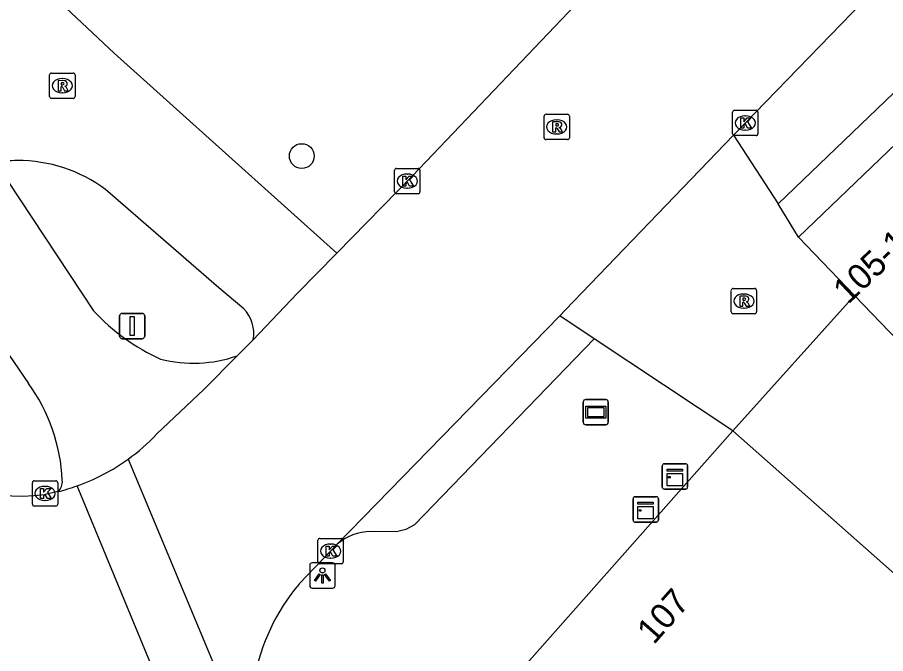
# Model space of a CAD drawing. Extents: x 162812 to 163818, y 381639 to 382470.
# Drawn here: x 162829.9 to 162864.17, y 382025.07 to 382050.18 of the extents above; entities that cross this region are included whole.
import ezdxf

# ---------------------------------------------------------------- set-up
doc = ezdxf.new("R2010")
doc.units = 0
for name, color, linetype in [('IMGEO_Boom', 7, 'Continuous'), ('IMGEO_Fietspad_open', 7, 'Continuous'), ('IMGEO_Kast', 7, 'Continuous'), ('IMGEO_Kolk', 7, 'Continuous'), ('IMGEO_Lichtpunt', 7, 'Continuous'), ('IMGEO_Pand', 7, 'Continuous'), ('IMGEO_Pand_nummerreeks', 7, 'Continuous'), ('IMGEO_Reclamebord', 7, 'Continuous'), ('IMGEO_Rijbaan_lokaal_gesloten', 7, 'Continuous'), ('IMGEO_Rijbaan_lokaal_open', 7, 'Continuous'), ('IMGEO_Rioolput', 7, 'Continuous'), ('IMGEO_Verkeersbordpaal', 7, 'Continuous'), ('IMGEO_Voetpad_open', 7, 'Continuous')]:
    doc.layers.add(name, color=color, linetype=linetype)

msp = doc.modelspace()

# ---------------------------------------------------------------- linework, layer by layer
at = {"layer": 'IMGEO_Boom'}
msp.add_circle((162841.123, 382044.707), 0.489, dxfattribs=at)
at = {"layer": 'IMGEO_Fietspad_open'}
for points in [[(162829.017, 382044.46), (162832.907, 382038.597)], [(162826.137, 382041.866), (162830.332, 382035.729)]]:
    msp.add_lwpolyline(points, dxfattribs=at)
for centre, radius, start, end in [((162838.94, 382044.182), 8.221, 222.7929, 245.6032), ((162836.846, 382041.784), 5.253, 255.653, 289.2539), ((162824.671, 382031.6), 7.007, 2.5444, 36.1079), ((162831.148, 382031.855), 0.526, 311.7184, 6.1382)]:
    msp.add_arc(centre, radius, start, end, dxfattribs=at)
at = {"layer": 'IMGEO_Kast'}
for p, q in [((162855.349, 382031.639), (162855.349, 382032.48)), ((162855.349, 382032.48), (162855.349, 382031.639)), ((162855.424, 382032.564), (162856.265, 382032.564)), ((162856.265, 382032.564), (162855.424, 382032.564)), ((162856.349, 382032.489), (162856.349, 382031.648)), ((162856.349, 382031.648), (162856.349, 382032.489)), ((162854.27, 382031.259), (162855.111, 382031.259)), ((162855.111, 382031.259), (162854.27, 382031.259)), ((162856.274, 382031.564), (162855.433, 382031.564)), ((162855.433, 382031.564), (162856.274, 382031.564)), ((162854.195, 382030.334), (162854.195, 382031.175)), ((162854.195, 382031.175), (162854.195, 382030.334)), ((162855.195, 382031.184), (162855.195, 382030.343)), ((162855.195, 382030.343), (162855.195, 382031.184)), ((162855.12, 382030.259), (162854.279, 382030.259)), ((162854.279, 382030.259), (162855.12, 382030.259))]:
    msp.add_line(p, q, dxfattribs=at)
for points in [[(162855.544, 382032.354), (162856.144, 382032.354), (162856.144, 382032.269), (162855.544, 382032.269), (162855.544, 382032.354)], [(162855.544, 382032.179), (162856.144, 382032.179), (162856.144, 382031.69), (162855.544, 382031.69), (162855.544, 382032.179)], [(162854.39, 382031.049), (162854.99, 382031.049), (162854.99, 382030.964), (162854.39, 382030.964), (162854.39, 382031.049)], [(162854.39, 382030.874), (162854.99, 382030.874), (162854.99, 382030.385), (162854.39, 382030.385), (162854.39, 382030.874)]]:
    msp.add_lwpolyline(points, dxfattribs=at)
for centre in [(162855.628, 382032.028), (162854.474, 382030.723)]:
    msp.add_circle(centre, 0.0377, dxfattribs=at)
for centre, start, end in [((162855.427, 382032.486), 92.4484, 184.2845), ((162855.427, 382032.486), 92.4484, 184.2845), ((162856.271, 382032.486), 2.4484, 94.2845), ((162856.271, 382032.486), 2.4484, 94.2845), ((162855.427, 382031.642), 182.4484, 274.2845), ((162855.427, 382031.642), 182.4484, 274.2845), ((162856.271, 382031.642), 272.4484, 4.2845), ((162856.271, 382031.642), 272.4484, 4.2845), ((162854.273, 382031.181), 92.4484, 184.2845), ((162854.273, 382031.181), 92.4484, 184.2845), ((162855.117, 382031.181), 2.4484, 94.2845), ((162855.117, 382031.181), 2.4484, 94.2845), ((162854.273, 382030.337), 182.4484, 274.2845), ((162854.273, 382030.337), 182.4484, 274.2845), ((162855.117, 382030.337), 272.4484, 4.2845), ((162855.117, 382030.337), 272.4484, 4.2845)]:
    msp.add_arc(centre, 0.0779, start, end, dxfattribs=at)
at = {"layer": 'IMGEO_Kolk'}
for p, q in [((162858.123, 382045.589), (162858.123, 382046.441)), ((162858.198, 382046.515), (162859.05, 382046.515)), ((162859.124, 382046.441), (162859.124, 382045.589)), ((162858.611, 382046.295), (162858.636, 382046.295)), ((162858.634, 382045.735), (162858.609, 382045.735)), ((162859.05, 382045.515), (162858.198, 382045.515)), ((162844.784, 382043.293), (162844.784, 382044.145)), ((162844.859, 382044.219), (162845.711, 382044.219)), ((162845.272, 382043.999), (162845.297, 382043.999)), ((162845.785, 382044.145), (162845.785, 382043.293)), ((162845.295, 382043.439), (162845.27, 382043.439)), ((162845.711, 382043.219), (162844.859, 382043.219)), ((162830.49, 382030.964), (162830.49, 382031.816)), ((162830.565, 382031.89), (162831.417, 382031.89)), ((162830.978, 382031.67), (162831.003, 382031.67)), ((162831.491, 382031.816), (162831.491, 382030.964)), ((162831.417, 382030.89), (162830.565, 382030.89)), ((162831.001, 382031.11), (162830.976, 382031.11)), ((162841.758, 382028.689), (162841.758, 382029.541)), ((162841.833, 382029.615), (162842.685, 382029.615)), ((162842.759, 382029.541), (162842.759, 382028.689)), ((162842.246, 382029.395), (162842.271, 382029.395)), ((162842.269, 382028.835), (162842.244, 382028.835)), ((162842.685, 382028.615), (162841.833, 382028.615))]:
    msp.add_line(p, q, dxfattribs=at)
for points in [[(162858.123, 382045.589), (162858.123, 382046.441)], [(162858.198, 382046.515), (162859.05, 382046.515)], [(162859.124, 382046.441), (162859.124, 382045.589)], [(162858.444, 382046.215), (162858.567, 382046.215), (162858.567, 382046.064), (162858.697, 382046.215), (162858.861, 382046.215), (162858.715, 382046.064), (162858.868, 382045.815), (162858.716, 382045.815), (162858.631, 382045.979), (162858.567, 382045.912), (162858.567, 382045.815), (162858.444, 382045.815), (162858.444, 382046.215)], [(162859.05, 382045.515), (162858.198, 382045.515)], [(162844.784, 382043.293), (162844.784, 382044.145)], [(162844.859, 382044.219), (162845.711, 382044.219)], [(162845.105, 382043.919), (162845.228, 382043.919), (162845.228, 382043.768), (162845.358, 382043.919), (162845.522, 382043.919), (162845.376, 382043.768), (162845.529, 382043.519), (162845.377, 382043.519), (162845.292, 382043.683), (162845.228, 382043.616), (162845.228, 382043.519), (162845.105, 382043.519), (162845.105, 382043.919)], [(162845.785, 382044.145), (162845.785, 382043.293)], [(162845.711, 382043.219), (162844.859, 382043.219)], [(162830.49, 382030.964), (162830.49, 382031.816)], [(162830.565, 382031.89), (162831.417, 382031.89)], [(162830.811, 382031.59), (162830.934, 382031.59), (162830.934, 382031.439), (162831.064, 382031.59), (162831.228, 382031.59), (162831.082, 382031.439), (162831.235, 382031.19), (162831.083, 382031.19), (162830.998, 382031.354), (162830.934, 382031.287), (162830.934, 382031.19), (162830.811, 382031.19), (162830.811, 382031.59)], [(162831.491, 382031.816), (162831.491, 382030.964)], [(162831.417, 382030.89), (162830.565, 382030.89)], [(162841.758, 382028.689), (162841.758, 382029.541)], [(162841.833, 382029.615), (162842.685, 382029.615)], [(162842.759, 382029.541), (162842.759, 382028.689)], [(162842.079, 382029.315), (162842.202, 382029.315), (162842.202, 382029.164), (162842.332, 382029.315), (162842.496, 382029.315), (162842.35, 382029.164), (162842.503, 382028.915), (162842.351, 382028.915), (162842.266, 382029.079), (162842.202, 382029.012), (162842.202, 382028.915), (162842.079, 382028.915), (162842.079, 382029.315)], [(162842.685, 382028.615), (162841.833, 382028.615)]]:
    msp.add_lwpolyline(points, dxfattribs=at)
for centre, start, end in [((162858.2, 382046.439), 91.552, 178.448), ((162858.2, 382046.439), 91.552, 178.448), ((162859.048, 382046.439), 1.552, 88.448), ((162859.048, 382046.439), 1.552, 88.448), ((162858.2, 382045.591), 181.552, 268.448), ((162858.2, 382045.591), 181.552, 268.448), ((162859.048, 382045.591), 271.552, 358.448), ((162859.048, 382045.591), 271.552, 358.448), ((162844.861, 382044.143), 91.552, 178.448), ((162844.861, 382044.143), 91.552, 178.448), ((162845.709, 382044.143), 1.552, 88.448), ((162845.709, 382044.143), 1.552, 88.448), ((162844.861, 382043.295), 181.552, 268.448), ((162844.861, 382043.295), 181.552, 268.448), ((162845.709, 382043.295), 271.552, 358.448), ((162845.709, 382043.295), 271.552, 358.448), ((162830.567, 382031.814), 91.552, 178.448), ((162830.567, 382031.814), 91.552, 178.448), ((162831.415, 382031.814), 1.552, 88.448), ((162831.415, 382031.814), 1.552, 88.448), ((162830.567, 382030.966), 181.552, 268.448), ((162830.567, 382030.966), 181.552, 268.448), ((162831.415, 382030.966), 271.552, 358.448), ((162831.415, 382030.966), 271.552, 358.448), ((162841.835, 382029.539), 91.552, 178.448), ((162841.835, 382029.539), 91.552, 178.448), ((162842.683, 382029.539), 1.552, 88.448), ((162842.683, 382029.539), 1.552, 88.448), ((162841.835, 382028.691), 181.552, 268.448), ((162841.835, 382028.691), 181.552, 268.448), ((162842.683, 382028.691), 271.552, 358.448), ((162842.683, 382028.691), 271.552, 358.448)]:
    msp.add_arc(centre, 0.0765, start, end, dxfattribs=at)
for centre, major_axis, ratio, start_param, end_param in [((162858.61, 382046.015), (-0.387, 0.002), 0.722429, 4.712389, 7.853982), ((162858.635, 382046.015), (-0.39, 0.002), 0.717154, 1.570796, 4.712389), ((162845.271, 382043.719), (-0.387, 0.002), 0.722429, 4.712389, 7.853982), ((162845.296, 382043.719), (-0.39, 0.002), 0.717154, 1.570796, 4.712389), ((162830.977, 382031.39), (-0.387, 0.002), 0.722429, 4.712389, 7.853982), ((162831.002, 382031.39), (-0.39, 0.002), 0.717154, 1.570796, 4.712389), ((162842.245, 382029.115), (-0.387, 0.002), 0.722429, 4.712389, 7.853982), ((162842.27, 382029.115), (-0.39, 0.002), 0.717154, 1.570796, 4.712389)]:
    msp.add_ellipse(centre, major_axis=major_axis, ratio=ratio, start_param=start_param, end_param=end_param, dxfattribs=at)
at = {"layer": 'IMGEO_Lichtpunt'}
for p, q in [((162841.438, 382028.557), (162841.438, 382027.75)), ((162841.438, 382028.557), (162841.438, 382027.75)), ((162842.34, 382028.652), (162841.532, 382028.652)), ((162842.34, 382028.652), (162841.532, 382028.652)), ((162842.434, 382027.75), (162842.434, 382028.557)), ((162842.434, 382027.75), (162842.434, 382028.557)), ((162841.532, 382027.656), (162842.34, 382027.656)), ((162841.532, 382027.656), (162842.34, 382027.656))]:
    msp.add_line(p, q, dxfattribs=at)
for points in [[(162841.812, 382028.221), (162841.851, 382028.193), (162841.663, 382027.931), (162841.625, 382027.958), (162841.812, 382028.221)], [(162841.914, 382028.173), (162841.961, 382028.173), (162841.961, 382027.851), (162841.914, 382027.851), (162841.914, 382028.173)], [(162842.024, 382028.193), (162842.062, 382028.22), (162842.249, 382027.958), (162842.21, 382027.93), (162842.024, 382028.193)]]:
    msp.add_lwpolyline(points, dxfattribs=at)
msp.add_circle((162841.937, 382028.355), 0.0994, dxfattribs=at)
for centre, start, end in [((162841.532, 382028.557), 90, 180), ((162841.532, 382028.557), 90, 180), ((162842.34, 382028.557), 0, 90), ((162842.34, 382028.557), 0, 90), ((162841.532, 382027.75), 180, 270), ((162841.532, 382027.75), 180, 270), ((162842.34, 382027.75), 270, 0), ((162842.34, 382027.75), 270, 360)]:
    msp.add_arc(centre, 0.0946, start, end, dxfattribs=at)
at = {"layer": 'IMGEO_Pand'}
for points in [[(162865.874, 382046.445), (162860.728, 382041.505)], [(162862.933, 382039.208), (162860.728, 382041.505)], [(162862.933, 382039.208), (162866.707, 382035.277)], [(162847.595, 382023.418), (162847.962, 382023.834), (162848.69, 382023.19), (162858.129, 382033.865)], [(162875.781, 382018.258), (162858.129, 382033.865)]]:
    msp.add_lwpolyline(points, dxfattribs=at)
at = {"layer": 'IMGEO_Reclamebord'}
for p, q in [((162852.23, 382034.198), (162852.23, 382034.998)), ((162852.23, 382034.998), (162852.23, 382034.198)), ((162852.33, 382035.098), (162853.12, 382035.098)), ((162853.12, 382035.098), (162852.33, 382035.098)), ((162853.22, 382034.998), (162853.22, 382034.198)), ((162853.22, 382034.198), (162853.22, 382034.998)), ((162853.12, 382034.098), (162852.33, 382034.098)), ((162852.33, 382034.098), (162853.12, 382034.098))]:
    msp.add_line(p, q, dxfattribs=at)
for points in [[(162852.331, 382034.83), (162853.119, 382034.83), (162853.119, 382034.366), (162852.331, 382034.366), (162852.331, 382034.83)], [(162852.396, 382034.765), (162852.396, 382034.431), (162853.054, 382034.431), (162853.054, 382034.765), (162852.396, 382034.765)]]:
    msp.add_lwpolyline(points, dxfattribs=at)
for centre, start, end in [((162852.33, 382034.998), 90, 180), ((162852.33, 382034.998), 90, 180), ((162853.12, 382034.998), 0, 90), ((162853.12, 382034.998), 360, 90), ((162852.33, 382034.198), 180, 270), ((162852.33, 382034.198), 180, 270), ((162853.12, 382034.198), 270, 0), ((162853.12, 382034.198), 270, 0)]:
    msp.add_arc(centre, 0.1, start, end, dxfattribs=at)
at = {"layer": 'IMGEO_Rijbaan_lokaal_gesloten'}
for points in [[(162858.156, 382045.535), (162863.261, 382050.801), (162876.36, 382064.246), (162887.329, 382075.655), (162896.559, 382085.045), (162901.469, 382090.121)], [(162860.165, 382059.115), (162851.91, 382050.669), (162845.49, 382043.926), (162842.499, 382040.872)], [(162851.304, 382038.405), (162851.517, 382038.623), (162858.156, 382045.535)], [(162839.208, 382037.457), (162840.941, 382039.281), (162842.499, 382040.872)], [(162842.516, 382029.384), (162851.304, 382038.405)], [(162838.578, 382036.825), (162839.208, 382037.457)], [(162838.578, 382036.825), (162837.253, 382035.497), (162835.403, 382033.742)], [(162834.265, 382032.743), (162839.6, 382019.977)], [(162885.252, 381973.726), (162865.128, 381991.442), (162848.757, 382005.325), (162842.115, 382011.816), (162839.461, 382015.662), (162836.599, 382021.189), (162832.263, 382031.692)], [(162831.498, 382031.462), (162830.992, 382031.355)], [(162841.015, 382027.817), (162842.254, 382029.116), (162842.516, 382029.384)]]:
    msp.add_lwpolyline(points, dxfattribs=at)
for centre, radius, start, end in [((162829.556, 382039.255), 8.036, 305.872, 316.6849), ((162829.982, 382039.01), 7.721, 225.6142, 277.5159), ((162829.593, 382039.211), 7.979, 289.5522, 305.8445), ((162829.651, 382038.991), 7.752, 283.7802, 289.687), ((162847.104, 382022.67), 7.973, 139.7946, 199.7437)]:
    msp.add_arc(centre, radius, start, end, dxfattribs=at)
at = {"layer": 'IMGEO_Rijbaan_lokaal_open'}
for points in [[(162858.156, 382045.535), (162859.922, 382042.828)], [(162860.728, 382041.505), (162859.922, 382042.828)], [(162858.129, 382033.865), (162862.933, 382039.208)], [(162852.661, 382037.495), (162851.304, 382038.405)], [(162858.129, 382033.865), (162852.661, 382037.495)]]:
    msp.add_lwpolyline(points, dxfattribs=at)
at = {"layer": 'IMGEO_Rioolput'}
for p, q in [((162831.171, 382047.059), (162831.171, 382047.911)), ((162831.246, 382047.985), (162832.098, 382047.985)), ((162831.659, 382047.765), (162831.684, 382047.765)), ((162832.172, 382047.911), (162832.172, 382047.059)), ((162831.682, 382047.205), (162831.657, 382047.205)), ((162832.098, 382046.985), (162831.246, 382046.985)), ((162850.761, 382046.359), (162851.613, 382046.359)), ((162850.686, 382045.433), (162850.686, 382046.285)), ((162851.174, 382046.139), (162851.199, 382046.139)), ((162851.687, 382046.285), (162851.687, 382045.433)), ((162851.613, 382045.359), (162850.761, 382045.359)), ((162851.197, 382045.579), (162851.172, 382045.579)), ((162858.144, 382039.482), (162858.996, 382039.482)), ((162858.069, 382038.556), (162858.069, 382039.408)), ((162858.557, 382039.262), (162858.582, 382039.262)), ((162859.07, 382039.408), (162859.07, 382038.556)), ((162858.996, 382038.482), (162858.144, 382038.482)), ((162858.58, 382038.702), (162858.555, 382038.702))]:
    msp.add_line(p, q, dxfattribs=at)
for points in [[(162831.171, 382047.059), (162831.171, 382047.911)], [(162831.246, 382047.985), (162832.098, 382047.985)], [(162831.76, 382047.683), (162831.508, 382047.685), (162831.508, 382047.285)], [(162832.172, 382047.911), (162832.172, 382047.059)], [(162831.508, 382047.285), (162831.632, 382047.285), (162831.632, 382047.447), (162831.643, 382047.447)], [(162831.686, 382047.604), (162831.632, 382047.604), (162831.632, 382047.523)], [(162831.632, 382047.523), (162831.684, 382047.523)], [(162831.69, 382047.418), (162831.761, 382047.285), (162831.901, 382047.285), (162831.836, 382047.411)], [(162832.098, 382046.985), (162831.246, 382046.985)], [(162850.761, 382046.359), (162851.613, 382046.359)], [(162850.686, 382045.433), (162850.686, 382046.285)], [(162851.275, 382046.057), (162851.023, 382046.059), (162851.023, 382045.659)], [(162851.201, 382045.978), (162851.147, 382045.978), (162851.147, 382045.897)], [(162851.687, 382046.285), (162851.687, 382045.433)], [(162851.023, 382045.659), (162851.147, 382045.659), (162851.147, 382045.821), (162851.158, 382045.821)], [(162851.147, 382045.897), (162851.199, 382045.897)], [(162851.205, 382045.792), (162851.276, 382045.659), (162851.416, 382045.659), (162851.351, 382045.785)], [(162851.613, 382045.359), (162850.761, 382045.359)], [(162858.144, 382039.482), (162858.996, 382039.482)], [(162858.069, 382038.556), (162858.069, 382039.408)], [(162858.658, 382039.18), (162858.406, 382039.182), (162858.406, 382038.782)], [(162859.07, 382039.408), (162859.07, 382038.556)], [(162858.406, 382038.782), (162858.53, 382038.782), (162858.53, 382038.944), (162858.541, 382038.944)], [(162858.584, 382039.101), (162858.53, 382039.101), (162858.53, 382039.02)], [(162858.53, 382039.02), (162858.582, 382039.02)], [(162858.588, 382038.915), (162858.659, 382038.782), (162858.799, 382038.782), (162858.734, 382038.908)], [(162858.996, 382038.482), (162858.144, 382038.482)]]:
    msp.add_lwpolyline(points, dxfattribs=at)
for centre, radius, start, end in [((162831.248, 382047.909), 0.0765, 91.552, 178.448), ((162831.248, 382047.909), 0.0765, 91.552, 178.448), ((162831.759, 382047.573), 0.109, 350.3612, 89.416), ((162832.096, 382047.909), 0.0765, 1.552, 88.448), ((162832.096, 382047.909), 0.0765, 1.552, 88.448), ((162831.642, 382047.394), 0.0533, 26.0293, 88.6989), ((162831.668, 382047.712), 0.19, 274.7715, 282.9687), ((162831.692, 382047.508), 0.0964, 77.0061, 93.1865), ((162831.706, 382047.565), 0.0378, 276.6634, 79.6772), ((162831.757, 382047.573), 0.112, 277.5842, 350.9817), ((162831.741, 382047.358), 0.108, 29.5134, 73.7905), ((162831.248, 382047.061), 0.0765, 181.552, 268.448), ((162831.248, 382047.061), 0.0765, 181.552, 268.448), ((162832.096, 382047.061), 0.0765, 271.552, 358.448), ((162832.096, 382047.061), 0.0765, 271.552, 358.448), ((162850.763, 382046.283), 0.0765, 91.552, 178.448), ((162850.763, 382046.283), 0.0765, 91.552, 178.448), ((162851.611, 382046.283), 0.0765, 1.552, 88.448), ((162851.611, 382046.283), 0.0765, 1.552, 88.448), ((162851.207, 382045.882), 0.0964, 77.0061, 93.1865), ((162851.221, 382045.939), 0.0378, 276.6634, 79.6772), ((162851.274, 382045.947), 0.109, 350.3612, 89.416), ((162851.157, 382045.768), 0.0533, 26.0293, 88.6989), ((162851.183, 382046.086), 0.19, 274.7715, 282.9687), ((162851.272, 382045.947), 0.112, 277.5842, 350.9817), ((162851.256, 382045.732), 0.108, 29.5134, 73.7905), ((162850.763, 382045.435), 0.0765, 181.552, 268.448), ((162850.763, 382045.435), 0.0765, 181.552, 268.448), ((162851.611, 382045.435), 0.0765, 271.552, 358.448), ((162851.611, 382045.435), 0.0765, 271.552, 358.448), ((162858.146, 382039.406), 0.0765, 91.552, 178.448), ((162858.146, 382039.406), 0.0765, 91.552, 178.448), ((162858.994, 382039.406), 0.0765, 1.552, 88.448), ((162858.994, 382039.406), 0.0765, 1.552, 88.448), ((162858.657, 382039.07), 0.109, 350.3612, 89.416), ((162858.54, 382038.891), 0.0533, 26.0293, 88.6989), ((162858.566, 382039.209), 0.19, 274.7715, 282.9687), ((162858.59, 382039.005), 0.0964, 77.0061, 93.1865), ((162858.604, 382039.062), 0.0378, 276.6634, 79.6772), ((162858.655, 382039.07), 0.112, 277.5842, 350.9817), ((162858.639, 382038.855), 0.108, 29.5134, 73.7905), ((162858.146, 382038.558), 0.0765, 181.552, 268.448), ((162858.146, 382038.558), 0.0765, 181.552, 268.448), ((162858.994, 382038.558), 0.0765, 271.552, 358.448), ((162858.994, 382038.558), 0.0765, 271.552, 358.448)]:
    msp.add_arc(centre, radius, start, end, dxfattribs=at)
for centre, major_axis, ratio, start_param, end_param in [((162831.658, 382047.485), (-0.387, 0.002), 0.722429, 4.712389, 7.853982), ((162831.683, 382047.485), (-0.39, 0.002), 0.717154, 1.570796, 4.712389), ((162851.173, 382045.859), (-0.387, 0.002), 0.722429, 4.712389, 7.853982), ((162851.198, 382045.859), (-0.39, 0.002), 0.717154, 1.570796, 4.712389), ((162858.556, 382038.982), (-0.387, 0.002), 0.722429, 4.712389, 7.853982), ((162858.581, 382038.982), (-0.39, 0.002), 0.717154, 1.570796, 4.712389)]:
    msp.add_ellipse(centre, major_axis=major_axis, ratio=ratio, start_param=start_param, end_param=end_param, dxfattribs=at)
at = {"layer": 'IMGEO_Verkeersbordpaal'}
for p, q in [((162834.033, 382038.498), (162834.823, 382038.498)), ((162834.823, 382038.498), (162834.033, 382038.498)), ((162833.933, 382037.598), (162833.933, 382038.398)), ((162833.933, 382038.398), (162833.933, 382037.598)), ((162834.923, 382038.398), (162834.923, 382037.598)), ((162834.923, 382037.598), (162834.923, 382038.398)), ((162834.823, 382037.498), (162834.033, 382037.498)), ((162834.033, 382037.498), (162834.823, 382037.498))]:
    msp.add_line(p, q, dxfattribs=at)
msp.add_lwpolyline([(162834.353, 382038.373), (162834.503, 382038.373), (162834.503, 382037.623), (162834.353, 382037.623), (162834.353, 382038.373)], dxfattribs=at)
for centre, start, end in [((162834.033, 382038.398), 90, 180), ((162834.033, 382038.398), 90, 180), ((162834.823, 382038.398), 0, 90), ((162834.823, 382038.398), 360, 90), ((162834.033, 382037.598), 180, 270), ((162834.033, 382037.598), 180, 270), ((162834.823, 382037.598), 270, 0), ((162834.823, 382037.598), 270, 0)]:
    msp.add_arc(centre, 0.1, start, end, dxfattribs=at)
at = {"layer": 'IMGEO_Voetpad_open'}
for points in [[(162859.922, 382042.828), (162890.165, 382071.854), (162891.17, 382070.73)], [(162842.499, 382040.872), (162833.723, 382048.763), (162830.307, 382051.984)], [(162838.833, 382038.683), (162837.844, 382039.513), (162833.379, 382043.387)], [(162852.661, 382037.495), (162845.577, 382030.15), (162845.233, 382029.969), (162844.86, 382029.871), (162843.844, 382029.893)]]:
    msp.add_lwpolyline(points, dxfattribs=at)
for centre, radius, start, end in [((162829.93, 382038.628), 5.903, 90.3245, 98.901), ((162829.925, 382038.746), 5.785, 53.3456, 90.2789), ((162837.828, 382037.705), 1.402, 349.793, 44.2219), ((162843.89, 382027.786), 2.107, 91.2508, 130.6912)]:
    msp.add_arc(centre, radius, start, end, dxfattribs=at)

# ---------------------------------------------------------------- texts
at = {"layer": 'IMGEO_Pand_nummerreeks'}
for s, rotation, p in [('105-105B', 43.4685, (162862.681, 382038.829)), ('107', 48.5164, (162855.013, 382025.391))]:
    msp.add_text(s, height=1, rotation=rotation, dxfattribs=at).set_placement(p)

doc.saveas('drawing.dxf')
